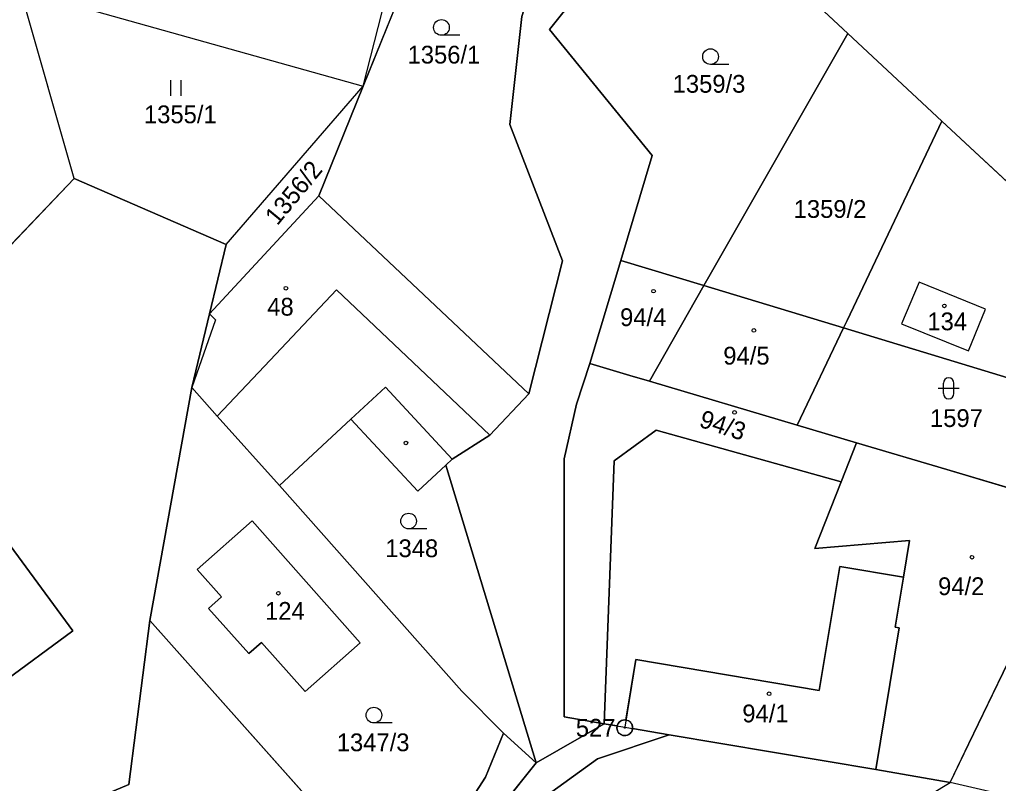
# Model space of a CAD drawing. Extents: x -760642 to -757221, y -1092371 to -1088855.
# Drawn here: x -758571.2 to -758477.6, y -1091565.5 to -1091492.4 of the extents above; entities that cross this region are included whole.
import ezdxf

# ---------------------------------------------------------------- set-up
doc = ezdxf.new("R2010")
doc.units = 0
for name, color, linetype in [('Vrstva 1', 7, 'Continuous'), ('Vrstva 17', 7, 'Continuous'), ('Vrstva 18', 7, 'Continuous'), ('Vrstva 19', 7, 'Continuous'), ('Vrstva 24', 7, 'Continuous'), ('Vrstva 25', 7, 'Continuous'), ('Vrstva 26', 7, 'Continuous'), ('Vrstva 27', 7, 'Continuous'), ('Vrstva 30', 7, 'Continuous'), ('Vrstva 4', 7, 'Continuous')]:
    doc.layers.add(name, color=color, linetype=linetype)

msp = doc.modelspace()

# ---------------------------------------------------------------- linework, layer by layer
at = {"layer": 'Vrstva 1'}
for p, q in [((-758538.34, -1091498.79), (-758529.64, -1091464.34)), ((-758538.34, -1091498.79), (-758525.24, -1091466.37)), ((-758508.55, -1091478.33), (-758520.53, -1091493.36)), ((-758492.01, -1091493.74), (-758503.35, -1091483.17)), ((-758571.13, -1091489.59), (-758538.34, -1091498.79)), ((-758566, -1091507.62), (-758571.13, -1091489.59)), ((-758523.16, -1091492.11), (-758524.32, -1091502.46)), ((-758520.53, -1091493.36), (-758510.7, -1091505.43)), ((-758492.01, -1091493.74), (-758505.15, -1091516.8)), ((-758483.01, -1091502.12), (-758492.01, -1091493.74)), ((-758551.46, -1091513.92), (-758538.34, -1091498.79)), ((-758542.58, -1091509.28), (-758538.34, -1091498.79)), ((-758524.32, -1091502.46), (-758519.29, -1091515.5)), ((-758492.08, -1091521.18), (-758483.01, -1091502.12)), ((-758467.28, -1091516.76), (-758483.01, -1091502.12)), ((-758510.7, -1091505.43), (-758513.71, -1091515.45)), ((-758575.77, -1091517.87), (-758566, -1091507.62)), ((-758566, -1091507.62), (-758551.46, -1091513.92)), ((-758542.58, -1091509.28), (-758553.05, -1091520.57)), ((-758522.51, -1091528.22), (-758542.58, -1091509.28)), ((-758551.46, -1091513.92), (-758553.05, -1091520.57)), ((-758519.29, -1091515.5), (-758522.51, -1091528.22)), ((-758513.71, -1091515.45), (-758516.67, -1091525.31)), ((-758505.76, -1091517.86), (-758513.71, -1091515.45)), ((-758505.15, -1091516.8), (-758505.76, -1091517.86)), ((-758485.17, -1091517.52), (-758486.86, -1091521.52)), ((-758478.82, -1091520.11), (-758485.17, -1091517.52)), ((-758505.76, -1091517.86), (-758510.97, -1091527)), ((-758492.43, -1091521.91), (-758505.76, -1091517.86)), ((-758480.45, -1091524.11), (-758478.82, -1091520.11)), ((-758553.05, -1091520.57), (-758554.74, -1091527.6)), ((-758492.43, -1091521.91), (-758492.08, -1091521.18)), ((-758496.85, -1091531.2), (-758492.43, -1091521.91)), ((-758465.39, -1091530.12), (-758492.43, -1091521.91)), ((-758486.86, -1091521.52), (-758480.45, -1091524.11)), ((-758516.67, -1091525.31), (-758517.96, -1091529.21)), ((-758512.84, -1091526.45), (-758516.67, -1091525.31)), ((-758510.97, -1091527), (-758512.84, -1091526.45)), ((-758558.74, -1091549.89), (-758554.74, -1091527.6)), ((-758554.74, -1091527.6), (-758552.3, -1091530.33)), ((-758496.85, -1091531.2), (-758510.97, -1091527)), ((-758526.22, -1091532.15), (-758522.51, -1091528.22)), ((-758517.96, -1091529.21), (-758519.13, -1091534.43)), ((-758552.3, -1091530.33), (-758546.36, -1091536.98)), ((-758546.36, -1091536.98), (-758539.52, -1091530.63)), ((-758539.52, -1091530.63), (-758533.12, -1091537.52)), ((-758491.18, -1091532.88), (-758496.85, -1091531.2)), ((-758526.22, -1091532.15), (-758529.83, -1091534.46)), ((-758510.33, -1091531.68), (-758514.33, -1091534.61)), ((-758510.33, -1091531.68), (-758492.63, -1091536.61)), ((-758491.18, -1091532.88), (-758492.63, -1091536.61)), ((-758482.54, -1091535.45), (-758491.18, -1091532.88)), ((-758519.13, -1091534.43), (-758519.13, -1091559.11)), ((-758533.12, -1091537.52), (-758530.43, -1091535.02)), ((-758530.43, -1091535.02), (-758529.83, -1091534.46)), ((-758521.8, -1091563.51), (-758530.43, -1091535.02)), ((-758514.33, -1091534.61), (-758515.29, -1091559.76)), ((-758469.62, -1091539.29), (-758482.54, -1091535.45)), ((-758546.36, -1091536.98), (-758528.9, -1091556.65)), ((-758492.63, -1091536.61), (-758495.17, -1091542.99)), ((-758566.11, -1091550.87), (-758575.47, -1091538.14)), ((-758480.42, -1091561.65), (-758469.62, -1091539.29)), ((-758554.23, -1091545), (-758548.95, -1091540.34)), ((-758548.95, -1091540.34), (-758538.62, -1091552.02)), ((-758495.17, -1091542.99), (-758486.09, -1091542.23)), ((-758486.09, -1091542.23), (-758486.67, -1091545.74)), ((-758551.89, -1091547.64), (-758554.23, -1091545)), ((-758487.46, -1091550.53), (-758486.67, -1091545.74)), ((-758553.13, -1091548.74), (-758551.89, -1091547.64)), ((-758549.27, -1091553.05), (-758553.13, -1091548.74)), ((-758558.74, -1091549.89), (-758560.77, -1091565.57)), ((-758537.71, -1091573.5), (-758558.74, -1091549.89)), ((-758573.04, -1091555.97), (-758566.11, -1091550.87)), ((-758489.33, -1091564.14), (-758487.08, -1091550.59)), ((-758487.08, -1091550.59), (-758487.46, -1091550.53)), ((-758548.06, -1091551.98), (-758549.27, -1091553.05)), ((-758543.89, -1091556.69), (-758548.06, -1091551.98)), ((-758538.62, -1091552.02), (-758543.89, -1091556.69)), ((-758528.9, -1091556.65), (-758524.93, -1091560.66)), ((-758519.13, -1091559.11), (-758515.29, -1091559.76)), ((-758524.93, -1091560.66), (-758526.65, -1091564.86)), ((-758521.8, -1091563.51), (-758524.93, -1091560.66)), ((-758515.29, -1091559.76), (-758521.8, -1091563.51)), ((-758515.29, -1091559.76), (-758513.34, -1091560.09)), ((-758513.34, -1091560.09), (-758509.1, -1091560.81)), ((-758515.95, -1091563.11), (-758509.1, -1091560.81)), ((-758509.1, -1091560.81), (-758489.33, -1091564.14)), ((-758482.2, -1091565.37), (-758480.42, -1091561.65)), ((-758521.44, -1091567.09), (-758515.95, -1091563.11)), ((-758521.8, -1091563.51), (-758525.12, -1091567.64)), ((-758489.33, -1091564.14), (-758482.2, -1091565.37)), ((-758526.65, -1091564.86), (-758527.94, -1091566.86)), ((-758423.8, -1091579.13), (-758482.2, -1091565.37))]:
    msp.add_line(p, q, dxfattribs=at)
at = {"layer": 'Vrstva 24'}
for radius in [0.75, 0.0327]:
    msp.add_circle((-758513.33, -1091560.15), radius, dxfattribs=at)
at = {"layer": 'Vrstva 25'}
for p, q in [((-758529.11, -1091493.92), (-758530.86, -1091493.92)), ((-758503.38, -1091496.71), (-758505.13, -1091496.71)), ((-758556.777, -1091498.215), (-758556.777, -1091499.715)), ((-758555.755, -1091499.715), (-758555.755, -1091498.215)), ((-758483.36, -1091527.68), (-758481.36, -1091527.68)), ((-758482.86, -1091528.18), (-758482.86, -1091527.18)), ((-758481.86, -1091528.18), (-758481.86, -1091527.18)), ((-758532.25, -1091541.13), (-758534, -1091541.13)), ((-758535.57, -1091559.69), (-758537.32, -1091559.69))]:
    msp.add_line(p, q, dxfattribs=at)
for centre, radius in [((-758530.86, -1091493.17), 0.75), ((-758505.13, -1091495.96), 0.75), ((-758545.74, -1091518.11), 0.175), ((-758510.58, -1091518.39), 0.175), ((-758482.77, -1091519.8), 0.175), ((-758500.98, -1091522.14), 0.175), ((-758502.83, -1091529.99), 0.175), ((-758534.26, -1091532.91), 0.175), ((-758534, -1091540.38), 0.75), ((-758480.13, -1091543.84), 0.175), ((-758546.46, -1091547.28), 0.175), ((-758499.53, -1091556.89), 0.175), ((-758537.32, -1091558.94), 0.75)]:
    msp.add_circle(centre, radius, dxfattribs=at)
for centre, start, end in [((-758482.36, -1091527.18), 0, 180), ((-758482.36, -1091528.18), 180, 0)]:
    msp.add_arc(centre, 0.5, start, end, dxfattribs=at)
at = {"layer": 'Vrstva 26'}
for points in [[(-758525.24, -1091466.37), (-758538.34, -1091498.79), (-758542.58, -1091509.28), (-758522.51, -1091528.22), (-758519.29, -1091515.5), (-758524.32, -1091502.46), (-758523.16, -1091492.11), (-758517.53, -1091474.2), (-758525.24, -1091466.37)], [(-758525.24, -1091466.37), (-758517.53, -1091474.2), (-758523.16, -1091492.11), (-758524.32, -1091502.46), (-758519.29, -1091515.5), (-758522.51, -1091528.22), (-758526.22, -1091532.15), (-758529.83, -1091534.46), (-758530.43, -1091535.02), (-758521.8, -1091563.51), (-758515.29, -1091559.76), (-758519.13, -1091559.11), (-758519.13, -1091534.43), (-758517.96, -1091529.21), (-758516.67, -1091525.31), (-758513.71, -1091515.45), (-758510.7, -1091505.43), (-758520.53, -1091493.36), (-758508.55, -1091478.33), (-758508.7, -1091469.23), (-758525.24, -1091466.37)], [(-758508.55, -1091478.33), (-758520.53, -1091493.36), (-758510.7, -1091505.43), (-758513.71, -1091515.45), (-758505.76, -1091517.86), (-758505.15, -1091516.8), (-758492.01, -1091493.74), (-758503.35, -1091483.17), (-758508.55, -1091478.33)], [(-758492.01, -1091493.74), (-758505.15, -1091516.8), (-758505.76, -1091517.86), (-758492.43, -1091521.91), (-758492.08, -1091521.18), (-758483.01, -1091502.12), (-758492.01, -1091493.74)], [(-758483.01, -1091502.12), (-758492.08, -1091521.18), (-758492.43, -1091521.91), (-758465.39, -1091530.12), (-758462.22, -1091523.46), (-758467.28, -1091516.76), (-758483.01, -1091502.12)], [(-758558.74, -1091549.89), (-758554.74, -1091527.6), (-758553.05, -1091520.57), (-758551.46, -1091513.92), (-758566, -1091507.62), (-758575.77, -1091517.87), (-758576.51, -1091518.65), (-758601.15, -1091527.44), (-758620.41, -1091533.51), (-758605.28, -1091551.08), (-758592.49, -1091542.44), (-758579.01, -1091533.34), (-758575.47, -1091538.14), (-758566.11, -1091550.87), (-758573.04, -1091555.97), (-758575.01, -1091557.42), (-758580.42, -1091550.16), (-758592.84, -1091558.78), (-758586.47, -1091575.92), (-758564.61, -1091567.19), (-758560.77, -1091565.57), (-758558.74, -1091549.89)], [(-758552.46, -1091521.13), (-758554.74, -1091527.6), (-758552.3, -1091530.33), (-758547.78, -1091525.55), (-758540.9, -1091518.27), (-758526.22, -1091532.15), (-758522.51, -1091528.22), (-758542.58, -1091509.28), (-758553.05, -1091520.57), (-758552.46, -1091521.13)], [(-758513.71, -1091515.45), (-758516.67, -1091525.31), (-758512.84, -1091526.45), (-758510.97, -1091527), (-758505.76, -1091517.86), (-758513.71, -1091515.45)], [(-758485.17, -1091517.52), (-758486.86, -1091521.52), (-758480.45, -1091524.11), (-758478.82, -1091520.11), (-758485.17, -1091517.52)], [(-758526.22, -1091532.15), (-758540.9, -1091518.27), (-758547.78, -1091525.55), (-758552.3, -1091530.33), (-758546.36, -1091536.98), (-758539.52, -1091530.63), (-758536.22, -1091527.57), (-758529.83, -1091534.46), (-758526.22, -1091532.15)], [(-758510.97, -1091527), (-758496.85, -1091531.2), (-758492.43, -1091521.91), (-758505.76, -1091517.86), (-758510.97, -1091527)], [(-758496.85, -1091531.2), (-758491.18, -1091532.88), (-758482.54, -1091535.45), (-758469.62, -1091539.29), (-758465.39, -1091530.12), (-758492.43, -1091521.91), (-758496.85, -1091531.2)], [(-758512.84, -1091526.45), (-758516.67, -1091525.31), (-758517.96, -1091529.21), (-758519.13, -1091534.43), (-758519.13, -1091559.11), (-758515.29, -1091559.76), (-758514.33, -1091534.61), (-758510.33, -1091531.68), (-758492.63, -1091536.61), (-758491.18, -1091532.88), (-758496.85, -1091531.2), (-758510.97, -1091527), (-758512.84, -1091526.45)], [(-758558.74, -1091549.89), (-758537.71, -1091573.5), (-758534.17, -1091570.23), (-758527.94, -1091566.86), (-758526.65, -1091564.86), (-758524.93, -1091560.66), (-758528.9, -1091556.65), (-758546.36, -1091536.98), (-758552.3, -1091530.33), (-758554.74, -1091527.6), (-758558.74, -1091549.89)], [(-758529.83, -1091534.46), (-758536.22, -1091527.57), (-758539.52, -1091530.63), (-758533.12, -1091537.52), (-758530.43, -1091535.02), (-758529.83, -1091534.46)], [(-758524.93, -1091560.66), (-758521.8, -1091563.51), (-758530.43, -1091535.02), (-758533.12, -1091537.52), (-758539.52, -1091530.63), (-758546.36, -1091536.98), (-758528.9, -1091556.65), (-758524.93, -1091560.66)], [(-758513.226, -1091559.407), (-758512.26, -1091553.61), (-758494.74, -1091556.58), (-758492.77, -1091544.72), (-758486.67, -1091545.74), (-758486.09, -1091542.23), (-758495.17, -1091542.99), (-758492.63, -1091536.61), (-758510.33, -1091531.68), (-758514.33, -1091534.61), (-758515.29, -1091559.76), (-758514.058, -1091559.969)], [(-758486.09, -1091542.23), (-758486.67, -1091545.74), (-758487.46, -1091550.53), (-758487.08, -1091550.59), (-758489.33, -1091564.14), (-758482.2, -1091565.37), (-758480.42, -1091561.65), (-758469.62, -1091539.29), (-758482.54, -1091535.45), (-758491.18, -1091532.88), (-758492.63, -1091536.61), (-758495.17, -1091542.99), (-758486.09, -1091542.23)], [(-758575.47, -1091538.14), (-758582.4, -1091543.24), (-758573.04, -1091555.97), (-758566.11, -1091550.87), (-758575.47, -1091538.14)], [(-758548.06, -1091551.98), (-758543.89, -1091556.69), (-758538.62, -1091552.02), (-758548.95, -1091540.34), (-758554.23, -1091545), (-758551.89, -1091547.64), (-758553.13, -1091548.74), (-758549.27, -1091553.05), (-758548.06, -1091551.98)], [(-758512.583, -1091560.219), (-758509.1, -1091560.81), (-758489.33, -1091564.14), (-758487.08, -1091550.59), (-758487.46, -1091550.53), (-758486.67, -1091545.74), (-758492.77, -1091544.72), (-758494.74, -1091556.58), (-758512.26, -1091553.61), (-758513.226, -1091559.407)], [(-758540.75, -1091589.7), (-758525.12, -1091567.64), (-758521.8, -1091563.51), (-758524.93, -1091560.66), (-758526.65, -1091564.86), (-758527.94, -1091566.86), (-758534.17, -1091570.23), (-758537.71, -1091573.5), (-758558.74, -1091549.89), (-758560.77, -1091565.57), (-758564.61, -1091567.19), (-758586.47, -1091575.92), (-758592.76, -1091577.88), (-758583.65, -1091604.35), (-758584.09, -1091606.5), (-758569.86, -1091593.15), (-758570.01, -1091584.63), (-758561, -1091580.35), (-758548.81, -1091576.27), (-758546.77, -1091581.73), (-758543.72, -1091583.45), (-758540.75, -1091589.7)], [(-758514.058, -1091559.969), (-758515.29, -1091559.76), (-758521.8, -1091563.51), (-758525.12, -1091567.64), (-758540.75, -1091589.7), (-758539.28, -1091602.17), (-758538.79, -1091606.37), (-758539.929, -1091613.333)], [(-758539.772, -1091613.402), (-758536.06, -1091605.52), (-758532.14, -1091596.15), (-758526.52, -1091576.68), (-758524.98, -1091571.78), (-758521.44, -1091567.09), (-758515.95, -1091563.11), (-758509.1, -1091560.81), (-758512.583, -1091560.219)], [(-758521.6, -1091627.71), (-758528.3, -1091615.3), (-758527.03, -1091614.04), (-758527.83, -1091613.56), (-758529.81, -1091612.38), (-758530.09, -1091612.21), (-758524.32, -1091596.98), (-758520.51, -1091577.32), (-758517.97, -1091572.52), (-758516.83, -1091571.33), (-758510.42, -1091569.17), (-758498.94, -1091571.14), (-758495.54, -1091571.78), (-758493.47, -1091572.17), (-758482.2, -1091565.37), (-758489.33, -1091564.14), (-758509.1, -1091560.81), (-758515.95, -1091563.11), (-758521.44, -1091567.09), (-758524.98, -1091571.78), (-758526.52, -1091576.68), (-758532.14, -1091596.15), (-758536.06, -1091605.52), (-758539.772, -1091613.402)]]:
    msp.add_lwpolyline(points, dxfattribs=at)
for start, end in [(82.04495, 165.99855), (0, 82.04495), (165.99855, 180), (180, 354.75785), (354.75785, 0)]:
    msp.add_arc((-758513.33, -1091560.15), 0.75, start, end, dxfattribs=at)
at = {"layer": 'Vrstva 27'}
for points in [[(-758525.24, -1091466.37), (-758538.34, -1091498.79), (-758542.58, -1091509.28), (-758553.05, -1091520.57), (-758551.46, -1091513.92), (-758566, -1091507.62), (-758575.77, -1091517.87), (-758579.77, -1091515.84), (-758594.278, -1091508.477), (-758596.54, -1091486.49)], [(-758467.28, -1091516.76), (-758483.01, -1091502.12), (-758492.01, -1091493.74), (-758508.55, -1091478.33)], [(-758478.2, -1091617.7), (-758481.5, -1091598.68), (-758481.93, -1091596.22), (-758497.97, -1091594.14), (-758509.79, -1091592.61), (-758493.47, -1091572.17), (-758482.2, -1091565.37), (-758469.62, -1091539.29)]]:
    msp.add_lwpolyline(points, dxfattribs=at)
at = {"layer": 'Vrstva 30'}
for points in [[(-758594.922, -1091502.221), (-758594.04, -1091508.58), (-758579.77, -1091515.84), (-758575.77, -1091517.87), (-758566, -1091507.62), (-758571.13, -1091489.59), (-758610.74, -1091430.03), (-758635.42, -1091398.76), (-758658.56, -1091403.48), (-758626.15, -1091449.51), (-758604.53, -1091472.05), (-758600.53, -1091480.16), (-758596.54, -1091486.49), (-758594.922, -1091502.221)], [(-758508.7, -1091469.23), (-758508.55, -1091478.33), (-758503.35, -1091483.17), (-758492.01, -1091493.74), (-758483.01, -1091502.12), (-758467.28, -1091516.76), (-758461.25, -1091521.35), (-758430.66, -1091538.42), (-758418.59, -1091530.76), (-758417.98, -1091522.55), (-758413.1, -1091521.32), (-758463.98, -1091475.25), (-758485.44, -1091455.74), (-758492.28, -1091452.15), (-758508.7, -1091469.23)], [(-758485.44, -1091455.74), (-758492.28, -1091452.15), (-758508.7, -1091469.23), (-758508.55, -1091478.33), (-758503.35, -1091483.17), (-758492.01, -1091493.74), (-758483.01, -1091502.12), (-758467.28, -1091516.76), (-758461.25, -1091521.35), (-758430.66, -1091538.42), (-758418.59, -1091530.76), (-758417.98, -1091522.55), (-758413.1, -1091521.32), (-758463.98, -1091475.25), (-758485.44, -1091455.74)]]:
    msp.add_lwpolyline(points, dxfattribs=at)
at = {"layer": 'Vrstva 4'}
for p, q in [((-758540.9, -1091518.27), (-758547.78, -1091525.55)), ((-758540.9, -1091518.27), (-758526.22, -1091532.15)), ((-758552.46, -1091521.13), (-758554.74, -1091527.6)), ((-758553.05, -1091520.57), (-758552.46, -1091521.13)), ((-758547.78, -1091525.55), (-758552.3, -1091530.33)), ((-758539.52, -1091530.63), (-758536.22, -1091527.57)), ((-758529.83, -1091534.46), (-758536.22, -1091527.57)), ((-758492.77, -1091544.72), (-758494.74, -1091556.58)), ((-758486.67, -1091545.74), (-758492.77, -1091544.72)), ((-758512.26, -1091553.61), (-758513.34, -1091560.09)), ((-758512.26, -1091553.61), (-758494.74, -1091556.58))]:
    msp.add_line(p, q, dxfattribs=at)

# ---------------------------------------------------------------- texts
at = {"layer": 'Vrstva 17'}
msp.add_text('527', height=1.7, dxfattribs=at).set_placement((-758518.015, -1091561))
at = {"layer": 'Vrstva 18'}
for s, p in [('1356/1', (-758534.102, -1091496.62)), ('1359/3', (-758508.75, -1091499.41)), ('1355/1', (-758559.31, -1091502.33)), ('1359/2', (-758497.18, -1091511.38)), ('1597', (-758484.141, -1091531.38)), ('1348', (-758536.23, -1091543.83)), ('1347/3', (-758540.87, -1091562.39))]:
    msp.add_text(s, height=1.7, dxfattribs=at).set_placement(p)
msp.add_text('1356/2', height=1.7, rotation=50.52042, dxfattribs=at).set_placement((-758546.56, -1091512.19))
at = {"layer": 'Vrstva 19'}
for s, p in [('48', (-758547.52, -1091520.73)), ('94/4', (-758513.78, -1091521.73)), ('134', (-758484.39, -1091522.13)), ('94/5', (-758503.91, -1091525.41)), ('94/2', (-758483.37, -1091547.46)), ('124', (-758547.73, -1091549.82)), ('94/1', (-758502.09, -1091559.63))]:
    msp.add_text(s, height=1.7, dxfattribs=at).set_placement(p)
msp.add_text('94/3', height=1.7, rotation=341.95419, dxfattribs=at).set_placement((-758506.32, -1091531.33))

doc.saveas('drawing.dxf')
